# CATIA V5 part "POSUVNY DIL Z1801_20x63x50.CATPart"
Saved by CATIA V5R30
Part number: POSUVNY DIL MENSI
Bounding box of the stored display mesh (mm): x -50 to 0, y 0 to 20, z -34.5 to 34.5
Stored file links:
  C:\Users\ondra\Desktop\PŘÍLOHA P III\CATIA\POSUVNY DIL Z1801_20x63x50.CATPart
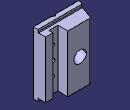
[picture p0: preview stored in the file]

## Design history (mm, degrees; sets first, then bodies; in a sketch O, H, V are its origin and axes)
Set1
  DatumSurface1 to DatumSurface34 "Z1801/20"
  Plane1: type Tangent, Support DatumSurface28, RefPoint vertex [face of DatumSurface34]
  Plane2: type Tangent, Support DatumSurface31, RefPoint vertex [face of DatumSurface24]
  Plane3: type Tangent, Support DatumSurface11, RefPoint vertex [face of DatumSurface7]
  Plane4: type Tangent, Support DatumSurface34, RefPoint vertex [face of DatumSurface26]
  Join1: Elements (DatumSurface1; DatumSurface2; DatumSurface3; DatumSurface4; DatumSurface5; DatumSurface6; DatumSurface7; DatumSurface8; DatumSurface9; DatumSurface10; DatumSurface11; DatumSurface12; DatumSurface13; DatumSurface14; DatumSurface15; DatumSurface16; DatumSurface17; DatumSurface18; DatumSurface19; DatumSurface20; DatumSurface21; DatumSurface22; DatumSurface23; DatumSurface24; DatumSurface25; DatumSurface26; DatumSurface27; DatumSurface28; DatumSurface29; DatumSurface30; DatumSurface31; DatumSurface32; DatumSurface33; DatumSurface34)
Body1 (main body)
  CloseSurface1: CloseElement Join1
  DatumCurve1
  Plane5: stored without definition
  Sketch1 on xy-plane, origin (0, 0, 0), H (1, 0, 0), V (0, 1, 0)
    reference projected line E1 (-50, 2) -> (-50, 0) from edge [face of CloseSurface1 | face of CloseSurface1]
    reference projected line E2 (-50, 0) -> (0, 0) from edge [face of CloseSurface1 | face of CloseSurface1]
    line L1 (-25, 0) -> (-22.3372, 1.6)
    point P7 (-25, 0)
    point P8 (-22.3372, 1.6)
    line L2 (-22.3372, 1.6) -> (-19.6743, 0)
    point P9 (-19.6743, 0)
    line L3 (-19.6743, 0) -> (-25, 0)
    point P10 (-19.6743, 0)
    construction line L4 (-22.3372, 1.6) -> (-22.3372, 0)
    point P11 (-22.3372, 0)
    distance P7 E1 = 25
    distance L3 P8 = 1.6
    angle L1 L2 = 118
    coincidence: P7 E2, P9 E2, P10 L2, P10 E2, P11 E2, P9 P10
    horizontal: L3 H
    vertical: L4 V
    symmetry: L2 L1 L4
  Pocket1: profile Sketch1, direction (0, 0, -1), through (limit type 6), opposite side through (limit type 6)
  DatumCurve2 to DatumCurve4
  Sketch2 on Plane5, origin (81.8218, 0, 0), H (0, 1, 0), V (0, 0, 1)
    reference projected line E1 (0.2152, 142.0375) -> (-1.7848, 142.0375) from edge of DatumCurve2
    reference projected line E2 (-1.7848, 142.0375) -> (-1.7848, 87.0375) from edge of DatumCurve3
    line L1 (-1.7848, 115.5375) -> (-0.1848, 112.8747)
    point P7 (-1.7848, 115.5375)
    point P8 (-0.1848, 112.8747)
    line L2 (-0.1848, 112.8747) -> (-1.7848, 110.2119)
    point P9 (-1.7848, 110.2119)
    line L3 (-1.7848, 110.2119) -> (-1.7848, 115.5375)
    construction line L4 (-0.1848, 112.8747) -> (-1.7848, 112.8747)
    point P10 (-1.7848, 112.8747)
    distance L3 P8 = 1.6
    angle L2 L1 = 118
    distance P7 E1 = 26.5
    coincidence: P7 E2, P9 E2, P10 L3
    vertical: L3 V
    horizontal: L4 H
    symmetry: L1 L2 L4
